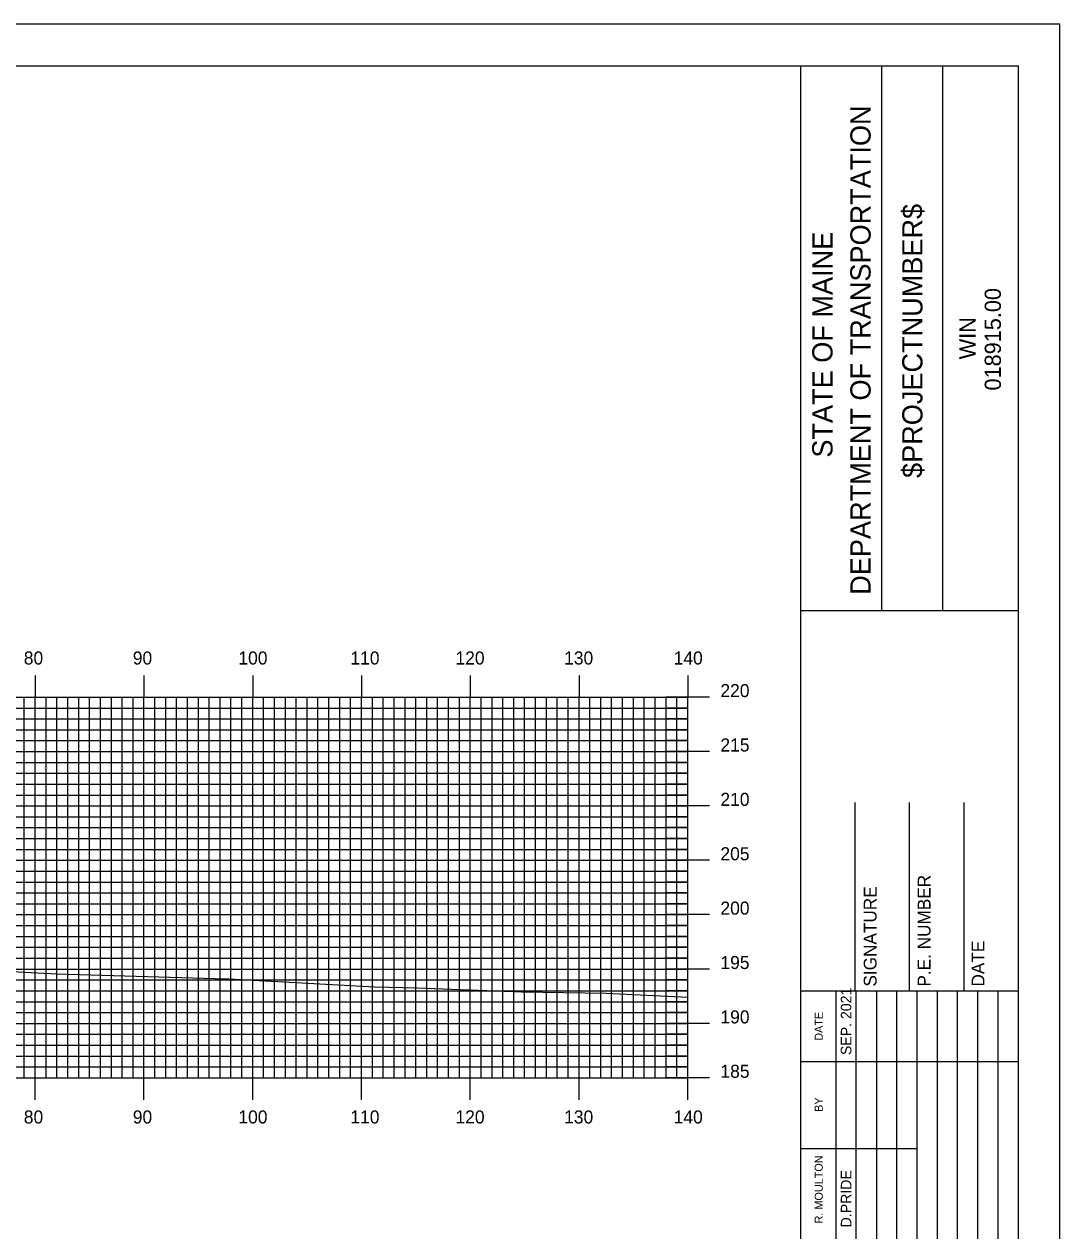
# Model space of a CAD drawing. Extents: x 1815702 to 1816046, y 442591 to 442811.
# Drawn here: x 1815947 to 1816042.3, y 442699.6 to 442810.5 of the extents above; entities that cross this region are included whole.
import ezdxf

# ---------------------------------------------------------------- set-up
doc = ezdxf.new("R2010")
doc.units = 0
for name, color, linetype in [('BORDER', 7, 'Continuous'), ('H_V ANNOTATION', 7, 'Continuous'), ('MAJOR', 7, 'Continuous'), ('MINOR', 7, 'Continuous'), ('PLOT BOUNDARY', 7, 'Continuous'), ('S_Roadway_Centerline', 7, 'Continuous')]:
    doc.layers.add(name, color=color, linetype=linetype)

msp = doc.modelspace()

# ---------------------------------------------------------------- linework, layer by layer
at = {"layer": 'BORDER'}
for p, q in [((1816018.45, 442596.67), (1816018.45, 442806.67)), ((1816025.9, 442756.66), (1816025.9, 442806.66)), ((1816031.49, 442756.66), (1816031.49, 442806.66)), ((1816018.45, 442756.65), (1816038.45, 442756.65)), ((1816023.45, 442721.67), (1816023.45, 442738.97)), ((1816028.45, 442721.67), (1816028.45, 442738.97)), ((1816033.45, 442721.67), (1816033.45, 442738.97)), ((1816018.45, 442721.67), (1816038.45, 442721.67))]:
    msp.add_line(p, q, dxfattribs=at)
msp.add_lwpolyline([(1815718.45, 442596.67), (1816038.45, 442596.67), (1816038.45, 442806.67), (1815718.45, 442806.67)], close=True, dxfattribs=at)
for points in [[(1816021.68, 442715.17), (1816021.68, 442721.67)], [(1816023.54, 442686.68), (1816023.54, 442721.67)], [(1816025.41, 442721.67), (1816025.41, 442686.68)], [(1816027.27, 442686.68), (1816027.27, 442721.67)], [(1816029.13, 442686.68), (1816029.13, 442721.67)], [(1816031, 442686.68), (1816031, 442721.67)], [(1816032.86, 442686.68), (1816032.86, 442721.67)], [(1816034.72, 442686.68), (1816034.72, 442721.67)], [(1816036.59, 442686.68), (1816036.59, 442721.67)], [(1816021.68, 442686.68), (1816021.68, 442720.26)], [(1816018.45, 442715.17), (1816038.45, 442715.17)], [(1816018.45, 442707.17), (1816021.68, 442707.17)], [(1816021.68, 442707.17), (1816029.13, 442707.17)]]:
    msp.add_lwpolyline(points, dxfattribs=at)
at = {"layer": 'MAJOR'}
for p, q in [((1815948.05, 442750.67), (1815948.05, 442748.67)), ((1815958.05, 442750.67), (1815958.05, 442748.67)), ((1815968.05, 442750.67), (1815968.05, 442748.67)), ((1815978.05, 442750.67), (1815978.05, 442748.67)), ((1815988.05, 442750.67), (1815988.05, 442748.67)), ((1815998.05, 442750.67), (1815998.05, 442748.67)), ((1816008.05, 442750.67), (1816008.05, 442748.67)), ((1815728.05, 442748.67), (1816008.05, 442748.67)), ((1815728.05, 442748.67), (1816008.05, 442748.67)), ((1815948.05, 442713.67), (1815948.05, 442748.67)), ((1815958.05, 442713.67), (1815958.05, 442748.67)), ((1815968.05, 442713.67), (1815968.05, 442748.67)), ((1815978.05, 442713.67), (1815978.05, 442748.67)), ((1815988.05, 442713.67), (1815988.05, 442748.67)), ((1815998.05, 442713.67), (1815998.05, 442748.67)), ((1816010.05, 442748.67), (1816006.04, 442748.67)), ((1816008.05, 442713.67), (1816008.05, 442748.67)), ((1816008.05, 442713.67), (1816008.05, 442748.67)), ((1815728.05, 442743.67), (1816008.05, 442743.67)), ((1816010.05, 442743.67), (1816006.04, 442743.67)), ((1815728.05, 442738.67), (1816008.05, 442738.67)), ((1816010.05, 442738.67), (1816006.04, 442738.67)), ((1815728.05, 442733.67), (1816008.05, 442733.67)), ((1816010.05, 442733.67), (1816006.04, 442733.67)), ((1815728.05, 442728.67), (1816008.05, 442728.67)), ((1816010.05, 442728.67), (1816006.04, 442728.67)), ((1815728.05, 442723.67), (1816008.05, 442723.67)), ((1816010.05, 442723.67), (1816006.04, 442723.67)), ((1815728.05, 442718.67), (1816008.05, 442718.67)), ((1816010.05, 442718.67), (1816006.04, 442718.67)), ((1815728.05, 442713.67), (1816008.05, 442713.67)), ((1815728.05, 442713.67), (1816008.05, 442713.67)), ((1815948.05, 442711.66), (1815948.05, 442713.67)), ((1815958.05, 442711.66), (1815958.05, 442713.67)), ((1815968.05, 442711.66), (1815968.05, 442713.67)), ((1815978.05, 442711.66), (1815978.05, 442713.67)), ((1815988.05, 442711.66), (1815988.05, 442713.67)), ((1815998.05, 442711.66), (1815998.05, 442713.67)), ((1816010.05, 442713.67), (1816006.04, 442713.67)), ((1816008.05, 442711.66), (1816008.05, 442713.67))]:
    msp.add_line(p, q, dxfattribs=at)
at = {"layer": 'MINOR'}
for p, q in [((1815947.05, 442713.67), (1815947.05, 442748.67)), ((1815949.05, 442713.67), (1815949.05, 442748.67)), ((1815950.05, 442713.67), (1815950.05, 442748.67)), ((1815951.05, 442713.67), (1815951.05, 442748.67)), ((1815952.05, 442713.67), (1815952.05, 442748.67)), ((1815953.05, 442713.67), (1815953.05, 442748.67)), ((1815954.05, 442713.67), (1815954.05, 442748.67)), ((1815955.05, 442713.67), (1815955.05, 442748.67)), ((1815956.05, 442713.67), (1815956.05, 442748.67)), ((1815957.05, 442713.67), (1815957.05, 442748.67)), ((1815959.05, 442713.67), (1815959.05, 442748.67)), ((1815960.05, 442713.67), (1815960.05, 442748.67)), ((1815961.05, 442713.67), (1815961.05, 442748.67)), ((1815962.05, 442713.67), (1815962.05, 442748.67)), ((1815963.05, 442713.67), (1815963.05, 442748.67)), ((1815964.05, 442713.67), (1815964.05, 442748.67)), ((1815965.05, 442713.67), (1815965.05, 442748.67)), ((1815966.05, 442713.67), (1815966.05, 442748.67)), ((1815967.05, 442713.67), (1815967.05, 442748.67)), ((1815969.05, 442713.67), (1815969.05, 442748.67)), ((1815970.05, 442713.67), (1815970.05, 442748.67)), ((1815971.05, 442713.67), (1815971.05, 442748.67)), ((1815972.05, 442713.67), (1815972.05, 442748.67)), ((1815973.05, 442713.67), (1815973.05, 442748.67)), ((1815974.05, 442713.67), (1815974.05, 442748.67)), ((1815975.05, 442713.67), (1815975.05, 442748.67)), ((1815976.05, 442713.67), (1815976.05, 442748.67)), ((1815977.05, 442713.67), (1815977.05, 442748.67)), ((1815979.05, 442713.67), (1815979.05, 442748.67)), ((1815980.05, 442713.67), (1815980.05, 442748.67)), ((1815981.05, 442713.67), (1815981.05, 442748.67)), ((1815982.05, 442713.67), (1815982.05, 442748.67)), ((1815983.05, 442713.67), (1815983.05, 442748.67)), ((1815984.05, 442713.67), (1815984.05, 442748.67)), ((1815985.05, 442713.67), (1815985.05, 442748.67)), ((1815986.05, 442713.67), (1815986.05, 442748.67)), ((1815987.05, 442713.67), (1815987.05, 442748.67)), ((1815989.05, 442713.67), (1815989.05, 442748.67)), ((1815990.05, 442713.67), (1815990.05, 442748.67)), ((1815991.05, 442713.67), (1815991.05, 442748.67)), ((1815992.05, 442713.67), (1815992.05, 442748.67)), ((1815993.05, 442713.67), (1815993.05, 442748.67)), ((1815994.05, 442713.67), (1815994.05, 442748.67)), ((1815995.05, 442713.67), (1815995.05, 442748.67)), ((1815996.05, 442713.67), (1815996.05, 442748.67)), ((1815997.05, 442713.67), (1815997.05, 442748.67)), ((1815999.05, 442713.67), (1815999.05, 442748.67)), ((1816000.05, 442713.67), (1816000.05, 442748.67)), ((1816001.05, 442713.67), (1816001.05, 442748.67)), ((1816002.05, 442713.67), (1816002.05, 442748.67)), ((1816003.05, 442713.67), (1816003.05, 442748.67)), ((1816004.05, 442713.67), (1816004.05, 442748.67)), ((1816005.05, 442713.67), (1816005.05, 442748.67)), ((1816006.05, 442713.67), (1816006.05, 442748.67)), ((1816007.05, 442713.67), (1816007.05, 442748.67)), ((1815728.05, 442747.67), (1816008.05, 442747.67)), ((1816008.05, 442747.67), (1816006.04, 442747.67)), ((1815728.05, 442746.67), (1816008.05, 442746.67)), ((1816008.05, 442746.67), (1816006.04, 442746.67)), ((1815728.05, 442745.67), (1816008.05, 442745.67)), ((1816008.05, 442745.67), (1816006.04, 442745.67)), ((1815728.05, 442744.67), (1816008.05, 442744.67)), ((1816008.05, 442744.67), (1816006.04, 442744.67)), ((1815728.05, 442742.67), (1816008.05, 442742.67)), ((1816008.05, 442742.67), (1816006.04, 442742.67)), ((1815728.05, 442741.67), (1816008.05, 442741.67)), ((1815728.05, 442740.67), (1816008.05, 442740.67)), ((1816008.05, 442741.67), (1816006.04, 442741.67)), ((1816008.05, 442740.67), (1816006.04, 442740.67)), ((1815728.05, 442739.67), (1816008.05, 442739.67)), ((1816008.05, 442739.67), (1816006.04, 442739.67)), ((1815728.05, 442737.67), (1816008.05, 442737.67)), ((1816008.05, 442737.67), (1816006.04, 442737.67)), ((1815728.05, 442736.67), (1816008.05, 442736.67)), ((1816008.05, 442736.67), (1816006.04, 442736.67)), ((1815728.05, 442735.67), (1816008.05, 442735.67)), ((1816008.05, 442735.67), (1816006.04, 442735.67)), ((1815728.05, 442734.67), (1816008.05, 442734.67)), ((1816008.05, 442734.67), (1816006.04, 442734.67)), ((1815728.05, 442732.67), (1816008.05, 442732.67)), ((1816008.05, 442732.67), (1816006.04, 442732.67)), ((1815728.05, 442731.67), (1816008.05, 442731.67)), ((1815728.05, 442730.67), (1816008.05, 442730.67)), ((1816008.05, 442731.67), (1816006.04, 442731.67)), ((1816008.05, 442730.67), (1816006.04, 442730.67)), ((1815728.05, 442729.67), (1816008.05, 442729.67)), ((1816008.05, 442729.67), (1816006.04, 442729.67)), ((1815728.05, 442727.67), (1816008.05, 442727.67)), ((1816008.05, 442727.67), (1816006.04, 442727.67)), ((1815728.05, 442726.67), (1816008.05, 442726.67)), ((1816008.05, 442726.67), (1816006.04, 442726.67)), ((1815728.05, 442725.67), (1816008.05, 442725.67)), ((1816008.05, 442725.67), (1816006.04, 442725.67)), ((1815728.05, 442724.67), (1816008.05, 442724.67)), ((1816008.05, 442724.67), (1816006.04, 442724.67)), ((1815728.05, 442722.67), (1816008.05, 442722.67)), ((1816008.05, 442722.67), (1816006.04, 442722.67)), ((1815728.05, 442721.67), (1816008.05, 442721.67)), ((1815728.05, 442720.67), (1816008.05, 442720.67)), ((1816008.05, 442721.67), (1816006.04, 442721.67)), ((1816008.05, 442720.67), (1816006.04, 442720.67)), ((1815728.05, 442719.67), (1816008.05, 442719.67)), ((1816008.05, 442719.67), (1816006.04, 442719.67)), ((1815728.05, 442717.67), (1816008.05, 442717.67)), ((1816008.05, 442717.67), (1816006.04, 442717.67)), ((1815728.05, 442716.67), (1816008.05, 442716.67)), ((1816008.05, 442716.67), (1816006.04, 442716.67)), ((1815728.05, 442715.67), (1816008.05, 442715.67)), ((1816008.05, 442715.67), (1816006.04, 442715.67)), ((1815728.05, 442714.67), (1816008.05, 442714.67)), ((1816008.05, 442714.67), (1816006.04, 442714.67))]:
    msp.add_line(p, q, dxfattribs=at)
at = {"layer": 'PLOT BOUNDARY'}
msp.add_lwpolyline([(1815702.26, 442590.55), (1816042.26, 442590.55), (1816042.26, 442810.55), (1815702.26, 442810.55)], close=True, dxfattribs=at)
at = {"layer": 'S_Roadway_Centerline'}
msp.add_lwpolyline([(1815944.06, 442723.54), (1815950.07, 442723.22), (1815965.64, 442722.77), (1815965.86, 442722.76), (1815979.25, 442722.03), (1815983.17, 442721.93), (1815992.77, 442721.57), (1816000.55, 442721.45), (1816008.05, 442721.09)], dxfattribs=at)

# ---------------------------------------------------------------- texts
at = {"layer": 'BORDER'}
for s, height, p in [('DEPARTMENT OF TRANSPORTATION', 1.8635, (1816024.86, 442758.08)), ('$PROJECTNUMBER$', 1.8635, (1816029.63, 442768.82)), ('STATE OF MAINE', 1.8635, (1816021.36, 442770.69)), ('018915.00', 1.491, (1816036.84, 442776.86)), ('WIN', 1.491, (1816034.52, 442779.73)), ('P.E. NUMBER', 1.1811, (1816030.37, 442722.06)), ('SIGNATURE', 1.181, (1816025.41, 442722.06)), ('DATE', 1.181, (1816035.33, 442722.06)), ('SEP. 2021', 0.969, (1816023.09, 442715.76)), ('DATE', 0.743, (1816020.46, 442717.08)), ('BY', 0.743, (1816020.46, 442710.54)), ('R. MOULTON', 0.745, (1816020.46, 442700.28)), ('D.PRIDE', 0.969, (1816023.09, 442699.92))]:
    msp.add_text(s, height=height, rotation=90, dxfattribs=at).set_placement(p)
at = {"layer": 'H_V ANNOTATION'}
for s, p in [('80', (1815947, 442751.67)), ('90', (1815957.02, 442751.67)), ('100', (1815966.73, 442751.67)), ('110', (1815977.03, 442751.67)), ('120', (1815986.69, 442751.67)), ('130', (1815996.68, 442751.67)), ('140', (1816006.75, 442751.67)), ('220', (1816011.05, 442748.67)), ('215', (1816011.05, 442743.67)), ('210', (1816011.05, 442738.67)), ('205', (1816011.05, 442733.67)), ('200', (1816011.05, 442728.67)), ('195', (1816011.05, 442723.67)), ('190', (1816011.05, 442718.67)), ('185', (1816011.05, 442713.67)), ('80', (1815947, 442709.47)), ('90', (1815957.02, 442709.47)), ('100', (1815966.73, 442709.47)), ('110', (1815977.03, 442709.47)), ('120', (1815986.69, 442709.47)), ('130', (1815996.68, 442709.47)), ('140', (1816006.75, 442709.47))]:
    msp.add_text(s, height=1.2, dxfattribs=at).set_placement(p)

doc.saveas('drawing.dxf')
